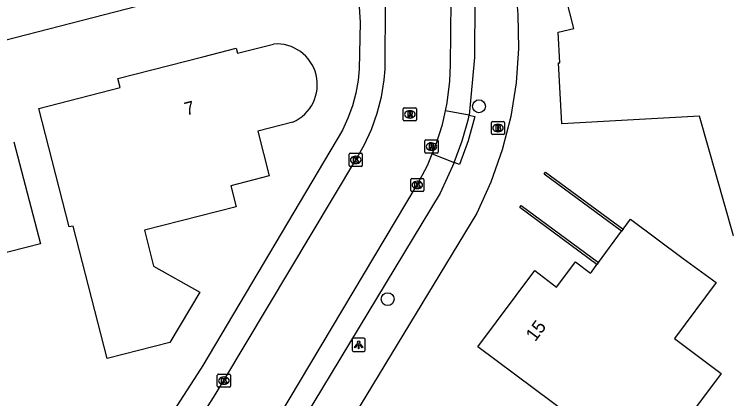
# Model space of a CAD drawing. Extents: x 158838 to 160074, y 386376 to 387776.
# Drawn here: x 159485.7 to 159539.8, y 386691 to 386720.2 of the extents above; entities that cross this region are included whole.
import ezdxf

# ---------------------------------------------------------------- set-up
doc = ezdxf.new("R2010")
doc.units = 0
for name, color, linetype in [('IMGEO_Boom', 7, 'Continuous'), ('IMGEO_Brandkraan', 7, 'Continuous'), ('IMGEO_Kolk', 7, 'Continuous'), ('IMGEO_Lichtpunt', 7, 'Continuous'), ('IMGEO_Muur', 7, 'Continuous'), ('IMGEO_Pand', 7, 'Continuous'), ('IMGEO_Pand_nummerreeks', 7, 'Continuous'), ('IMGEO_Rijbaan_lokaal_gesloten', 7, 'Continuous'), ('IMGEO_Rioolput', 7, 'Continuous'), ('IMGEO_Voetpad_open', 7, 'Continuous')]:
    doc.layers.add(name, color=color, linetype=linetype)

msp = doc.modelspace()

# ---------------------------------------------------------------- linework, layer by layer
at = {"layer": 'IMGEO_Boom'}
for centre in [(159520.987, 386713.228), (159514.05, 386698.566)]:
    msp.add_circle(centre, 0.489, dxfattribs=at)
at = {"layer": 'IMGEO_Brandkraan'}
for p, q in [((159521.933, 386711.149), (159521.933, 386712.001)), ((159522.008, 386712.075), (159522.86, 386712.075)), ((159522.421, 386711.855), (159522.446, 386711.855)), ((159522.934, 386712.001), (159522.934, 386711.149)), ((159522.86, 386711.075), (159522.008, 386711.075)), ((159522.444, 386711.295), (159522.419, 386711.295))]:
    msp.add_line(p, q, dxfattribs=at)
for points in [[(159521.933, 386711.149), (159521.933, 386712.001)], [(159522.008, 386712.075), (159522.86, 386712.075)], [(159522.281, 386711.775), (159522.281, 386711.375), (159522.494, 386711.375)], [(159522.512, 386711.775), (159522.281, 386711.775)], [(159522.46, 386711.694), (159522.406, 386711.694), (159522.406, 386711.618)], [(159522.406, 386711.618), (159522.459, 386711.618)], [(159522.934, 386712.001), (159522.934, 386711.149)], [(159522.86, 386711.075), (159522.008, 386711.075)], [(159522.468, 386711.542), (159522.406, 386711.542), (159522.406, 386711.461)], [(159522.406, 386711.461), (159522.468, 386711.461)]]:
    msp.add_lwpolyline(points, dxfattribs=at)
for centre, radius, start, end in [((159522.01, 386711.999), 0.0765, 91.552, 178.448), ((159522.01, 386711.999), 0.0765, 91.552, 178.448), ((159522.461, 386711.656), 0.0379, 267.8285, 90.9355), ((159522.516, 386711.63), 0.145, 59.4692, 91.5367), ((159522.541, 386711.677), 0.0922, 285.5137, 58.1501), ((159522.546, 386711.485), 0.105, 301.3115, 78.989), ((159522.858, 386711.999), 0.0765, 1.552, 88.448), ((159522.858, 386711.999), 0.0765, 1.552, 88.448), ((159522.01, 386711.151), 0.0765, 181.552, 268.448), ((159522.01, 386711.151), 0.0765, 181.552, 268.448), ((159522.469, 386711.501), 0.0404, 269.8759, 90.5077), ((159522.5, 386711.626), 0.251, 268.6676, 293.5347), ((159522.858, 386711.151), 0.0765, 271.552, 358.448), ((159522.858, 386711.151), 0.0765, 271.552, 358.448)]:
    msp.add_arc(centre, radius, start, end, dxfattribs=at)
for centre, major_axis, ratio, start_param, end_param in [((159522.42, 386711.575), (-0.387, 0.002), 0.722429, 4.712389, 7.853982), ((159522.445, 386711.575), (-0.39, 0.002), 0.717154, 1.570796, 4.712389)]:
    msp.add_ellipse(centre, major_axis=major_axis, ratio=ratio, start_param=start_param, end_param=end_param, dxfattribs=at)
at = {"layer": 'IMGEO_Kolk'}
for p, q in [((159511.123, 386708.725), (159511.123, 386709.577)), ((159511.198, 386709.651), (159512.05, 386709.651)), ((159511.611, 386709.431), (159511.636, 386709.431)), ((159512.124, 386709.577), (159512.124, 386708.725)), ((159512.05, 386708.651), (159511.198, 386708.651)), ((159511.634, 386708.871), (159511.609, 386708.871)), ((159515.803, 386706.819), (159515.803, 386707.671)), ((159515.878, 386707.745), (159516.73, 386707.745)), ((159516.291, 386707.525), (159516.316, 386707.525)), ((159516.804, 386707.671), (159516.804, 386706.819)), ((159516.73, 386706.745), (159515.878, 386706.745)), ((159516.314, 386706.965), (159516.289, 386706.965)), ((159501.108, 386691.946), (159501.108, 386692.798)), ((159501.183, 386692.872), (159502.035, 386692.872)), ((159501.596, 386692.652), (159501.621, 386692.652)), ((159502.109, 386692.798), (159502.109, 386691.946)), ((159501.619, 386692.092), (159501.594, 386692.092)), ((159502.035, 386691.872), (159501.183, 386691.872))]:
    msp.add_line(p, q, dxfattribs=at)
for points in [[(159511.123, 386708.725), (159511.123, 386709.577)], [(159511.198, 386709.651), (159512.05, 386709.651)], [(159512.124, 386709.577), (159512.124, 386708.725)], [(159511.444, 386709.351), (159511.567, 386709.351), (159511.567, 386709.2), (159511.697, 386709.351), (159511.861, 386709.351), (159511.715, 386709.2), (159511.868, 386708.951), (159511.716, 386708.951), (159511.631, 386709.115), (159511.567, 386709.048), (159511.567, 386708.951), (159511.444, 386708.951), (159511.444, 386709.351)], [(159512.05, 386708.651), (159511.198, 386708.651)], [(159515.803, 386706.819), (159515.803, 386707.671)], [(159515.878, 386707.745), (159516.73, 386707.745)], [(159516.124, 386707.445), (159516.247, 386707.445), (159516.247, 386707.294), (159516.377, 386707.445), (159516.541, 386707.445), (159516.395, 386707.294), (159516.548, 386707.045), (159516.396, 386707.045), (159516.311, 386707.209), (159516.247, 386707.142), (159516.247, 386707.045), (159516.124, 386707.045), (159516.124, 386707.445)], [(159516.804, 386707.671), (159516.804, 386706.819)], [(159516.73, 386706.745), (159515.878, 386706.745)], [(159501.108, 386691.946), (159501.108, 386692.798)], [(159501.183, 386692.872), (159502.035, 386692.872)], [(159502.109, 386692.798), (159502.109, 386691.946)], [(159501.429, 386692.572), (159501.552, 386692.572), (159501.552, 386692.421), (159501.682, 386692.572), (159501.846, 386692.572), (159501.7, 386692.421), (159501.853, 386692.172), (159501.701, 386692.172), (159501.616, 386692.336), (159501.552, 386692.269), (159501.552, 386692.172), (159501.429, 386692.172), (159501.429, 386692.572)], [(159502.035, 386691.872), (159501.183, 386691.872)]]:
    msp.add_lwpolyline(points, dxfattribs=at)
for centre, start, end in [((159511.2, 386709.575), 91.552, 178.448), ((159511.2, 386709.575), 91.552, 178.448), ((159512.048, 386709.575), 1.552, 88.448), ((159512.048, 386709.575), 1.552, 88.448), ((159511.2, 386708.727), 181.552, 268.448), ((159511.2, 386708.727), 181.552, 268.448), ((159512.048, 386708.727), 271.552, 358.448), ((159512.048, 386708.727), 271.552, 358.448), ((159515.88, 386707.669), 91.552, 178.448), ((159515.88, 386707.669), 91.552, 178.448), ((159516.728, 386707.669), 1.552, 88.448), ((159516.728, 386707.669), 1.552, 88.448), ((159515.88, 386706.821), 181.552, 268.448), ((159515.88, 386706.821), 181.552, 268.448), ((159516.728, 386706.821), 271.552, 358.448), ((159516.728, 386706.821), 271.552, 358.448), ((159501.185, 386692.796), 91.552, 178.448), ((159501.185, 386692.796), 91.552, 178.448), ((159502.033, 386692.796), 1.552, 88.448), ((159502.033, 386692.796), 1.552, 88.448), ((159501.185, 386691.948), 181.552, 268.448), ((159501.185, 386691.948), 181.552, 268.448), ((159502.033, 386691.948), 271.552, 358.448), ((159502.033, 386691.948), 271.552, 358.448)]:
    msp.add_arc(centre, 0.0765, start, end, dxfattribs=at)
for centre, major_axis, ratio, start_param, end_param in [((159511.61, 386709.151), (-0.387, 0.002), 0.722429, 4.712389, 7.853982), ((159511.635, 386709.151), (-0.39, 0.002), 0.717154, 1.570796, 4.712389), ((159516.29, 386707.245), (-0.387, 0.002), 0.722429, 4.712389, 7.853982), ((159516.315, 386707.245), (-0.39, 0.002), 0.717154, 1.570796, 4.712389), ((159501.595, 386692.372), (-0.387, 0.002), 0.722429, 4.712389, 7.853982), ((159501.62, 386692.372), (-0.39, 0.002), 0.717154, 1.570796, 4.712389)]:
    msp.add_ellipse(centre, major_axis=major_axis, ratio=ratio, start_param=start_param, end_param=end_param, dxfattribs=at)
at = {"layer": 'IMGEO_Lichtpunt'}
for p, q in [((159511.347, 386695.499), (159511.347, 386694.692)), ((159511.347, 386695.499), (159511.347, 386694.692)), ((159512.249, 386695.594), (159511.441, 386695.594)), ((159512.249, 386695.594), (159511.441, 386695.594)), ((159512.343, 386694.692), (159512.343, 386695.499)), ((159512.343, 386694.692), (159512.343, 386695.499)), ((159511.441, 386694.598), (159512.249, 386694.598)), ((159511.441, 386694.598), (159512.249, 386694.598))]:
    msp.add_line(p, q, dxfattribs=at)
for points in [[(159511.721, 386695.163), (159511.76, 386695.135), (159511.572, 386694.873), (159511.534, 386694.9), (159511.721, 386695.163)], [(159511.823, 386695.115), (159511.87, 386695.115), (159511.87, 386694.793), (159511.823, 386694.793), (159511.823, 386695.115)], [(159511.933, 386695.135), (159511.971, 386695.162), (159512.158, 386694.9), (159512.119, 386694.872), (159511.933, 386695.135)]]:
    msp.add_lwpolyline(points, dxfattribs=at)
msp.add_circle((159511.846, 386695.297), 0.0994, dxfattribs=at)
for centre, start, end in [((159511.441, 386695.499), 90, 180), ((159511.441, 386695.499), 90, 180), ((159512.249, 386695.499), 0, 90), ((159512.249, 386695.499), 0, 90), ((159511.441, 386694.692), 180, 270), ((159511.441, 386694.692), 180, 270), ((159512.249, 386694.692), 270, 0), ((159512.249, 386694.692), 270, 360)]:
    msp.add_arc(centre, 0.0946, start, end, dxfattribs=at)
at = {"layer": 'IMGEO_Muur'}
for points in [[(159531.824, 386703.734), (159525.942, 386708.073), (159526.048, 386708.213), (159531.942, 386703.893)], [(159529.95, 386701.192), (159524.08, 386705.521), (159524.184, 386705.68), (159530.062, 386701.345)]]:
    msp.add_lwpolyline(points, dxfattribs=at)
at = {"layer": 'IMGEO_Pand'}
for points in [[(159546.149, 386705.02), (159540.327, 386703.374), (159537.752, 386712.48), (159532.281, 386712.169), (159527.289, 386711.885), (159527.025, 386716.527), (159527.131, 386716.528), (159526.993, 386718.851), (159528.19, 386719.148), (159526.968, 386723.917), (159533.73, 386725.646), (159533.978, 386724.677), (159536.711, 386725.424), (159540.305, 386726.406), (159541.623, 386721.583), (159546.149, 386705.02)], [(159487.54, 386713.069), (159493.724, 386714.655), (159493.557, 386715.329), (159500, 386716.992), (159502.548, 386717.65), (159502.648, 386717.262), (159505.369, 386717.958)], [(159506.842, 386712.025), (159504.174, 386711.333), (159505.041, 386707.931), (159502.142, 386707.192), (159502.549, 386705.593), (159495.577, 386703.817), (159496.269, 386701.084), (159499.767, 386699.087), (159497.488, 386695.274), (159492.734, 386694.053), (159490.144, 386704.126), (159489.853, 386704.051), (159487.54, 386713.069)], [(159485.637, 386710.52), (159487.661, 386702.78), (159484.167, 386701.875)], [(159531.942, 386703.893), (159532.489, 386704.635), (159536.513, 386701.667), (159539.016, 386699.821), (159535.837, 386695.571), (159539.38, 386692.921), (159533.731, 386685.37), (159520.906, 386694.932), (159525.234, 386700.736), (159526.889, 386699.484), (159528.185, 386701.234), (159528.311, 386701.404), (159529.466, 386700.536), (159529.526, 386700.618), (159529.95, 386701.192)], [(159530.062, 386701.345), (159531.824, 386703.734)], [(159531.942, 386703.893), (159531.824, 386703.734)], [(159530.062, 386701.345), (159529.95, 386701.192)]]:
    msp.add_lwpolyline(points, dxfattribs=at)
msp.add_arc((159505.603, 386714.867), 3.1, 293.5507, 94.3354, dxfattribs=at)
at = {"layer": 'IMGEO_Rijbaan_lokaal_gesloten'}
for points in [[(159499.36, 386688.811), (159500, 386689.822), (159500.806, 386691.095), (159501.61, 386692.371), (159511.626, 386709.15), (159512.275, 386710.281), (159512.821, 386711.465), (159513.258, 386712.692), (159513.584, 386713.955), (159513.796, 386715.241), (159513.869, 386716.038), (159513.878, 386721.278), (159513.757, 386723.28), (159513.538, 386725.199)], [(159518.439, 386712.887), (159518.568, 386713.481), (159518.776, 386715.135), (159518.834, 386716.37), (159518.864, 386721.239), (159518.731, 386723.49), (159518.576, 386725.587)], [(159517.443, 386709.606), (159517.715, 386710.261), (159518.213, 386711.852), (159518.439, 386712.887)], [(159502.694, 386684.743), (159505.787, 386689.619), (159516.302, 386707.245), (159517.076, 386708.722), (159517.443, 386709.606)]]:
    msp.add_lwpolyline(points, dxfattribs=at)
at = {"layer": 'IMGEO_Rioolput'}
for p, q in [((159515.239, 386712.186), (159515.239, 386713.038)), ((159515.314, 386713.112), (159516.166, 386713.112)), ((159515.727, 386712.892), (159515.752, 386712.892)), ((159516.24, 386713.038), (159516.24, 386712.186)), ((159515.75, 386712.332), (159515.725, 386712.332)), ((159516.166, 386712.112), (159515.314, 386712.112)), ((159516.877, 386709.739), (159516.877, 386710.591)), ((159516.952, 386710.665), (159517.804, 386710.665)), ((159517.878, 386710.591), (159517.878, 386709.739)), ((159517.365, 386710.445), (159517.39, 386710.445)), ((159517.804, 386709.665), (159516.952, 386709.665)), ((159517.388, 386709.885), (159517.363, 386709.885))]:
    msp.add_line(p, q, dxfattribs=at)
for points in [[(159515.239, 386712.186), (159515.239, 386713.038)], [(159515.314, 386713.112), (159516.166, 386713.112)], [(159515.828, 386712.81), (159515.576, 386712.812), (159515.576, 386712.412)], [(159515.754, 386712.731), (159515.7, 386712.731), (159515.7, 386712.65)], [(159516.24, 386713.038), (159516.24, 386712.186)], [(159515.576, 386712.412), (159515.7, 386712.412), (159515.7, 386712.574), (159515.711, 386712.574)], [(159515.7, 386712.65), (159515.752, 386712.65)], [(159515.758, 386712.545), (159515.829, 386712.412), (159515.969, 386712.412), (159515.904, 386712.538)], [(159516.166, 386712.112), (159515.314, 386712.112)], [(159516.877, 386709.739), (159516.877, 386710.591)], [(159516.952, 386710.665), (159517.804, 386710.665)], [(159517.878, 386710.591), (159517.878, 386709.739)], [(159517.466, 386710.363), (159517.214, 386710.365), (159517.214, 386709.965)], [(159517.214, 386709.965), (159517.338, 386709.965), (159517.338, 386710.127), (159517.349, 386710.127)], [(159517.392, 386710.284), (159517.338, 386710.284), (159517.338, 386710.203)], [(159517.338, 386710.203), (159517.39, 386710.203)], [(159517.396, 386710.098), (159517.467, 386709.965), (159517.607, 386709.965), (159517.542, 386710.091)], [(159517.804, 386709.665), (159516.952, 386709.665)]]:
    msp.add_lwpolyline(points, dxfattribs=at)
for centre, radius, start, end in [((159515.316, 386713.036), 0.0765, 91.552, 178.448), ((159515.316, 386713.036), 0.0765, 91.552, 178.448), ((159515.76, 386712.635), 0.0964, 77.0061, 93.1865), ((159515.774, 386712.692), 0.0378, 276.6634, 79.6772), ((159515.827, 386712.7), 0.109, 350.3612, 89.416), ((159515.825, 386712.7), 0.112, 277.5842, 350.9817), ((159516.164, 386713.036), 0.0765, 1.552, 88.448), ((159516.164, 386713.036), 0.0765, 1.552, 88.448), ((159515.316, 386712.188), 0.0765, 181.552, 268.448), ((159515.316, 386712.188), 0.0765, 181.552, 268.448), ((159515.71, 386712.521), 0.0533, 26.0293, 88.6989), ((159515.736, 386712.839), 0.19, 274.7715, 282.9687), ((159515.809, 386712.485), 0.108, 29.5134, 73.7905), ((159516.164, 386712.188), 0.0765, 271.552, 358.448), ((159516.164, 386712.188), 0.0765, 271.552, 358.448), ((159516.954, 386710.589), 0.0765, 91.552, 178.448), ((159516.954, 386710.589), 0.0765, 91.552, 178.448), ((159517.802, 386710.589), 0.0765, 1.552, 88.448), ((159517.802, 386710.589), 0.0765, 1.552, 88.448), ((159517.348, 386710.074), 0.0533, 26.0293, 88.6989), ((159517.374, 386710.392), 0.19, 274.7715, 282.9687), ((159517.398, 386710.188), 0.0964, 77.0061, 93.1865), ((159517.412, 386710.245), 0.0378, 276.6634, 79.6772), ((159517.465, 386710.253), 0.109, 350.3612, 89.416), ((159517.463, 386710.253), 0.112, 277.5842, 350.9817), ((159517.447, 386710.038), 0.108, 29.5134, 73.7905), ((159516.954, 386709.741), 0.0765, 181.552, 268.448), ((159516.954, 386709.741), 0.0765, 181.552, 268.448), ((159517.802, 386709.741), 0.0765, 271.552, 358.448), ((159517.802, 386709.741), 0.0765, 271.552, 358.448)]:
    msp.add_arc(centre, radius, start, end, dxfattribs=at)
for centre, major_axis, ratio, start_param, end_param in [((159515.726, 386712.612), (-0.387, 0.002), 0.722429, 4.712389, 7.853982), ((159515.751, 386712.612), (-0.39, 0.002), 0.717154, 1.570796, 4.712389), ((159517.364, 386710.165), (-0.387, 0.002), 0.722429, 4.712389, 7.853982), ((159517.389, 386710.165), (-0.39, 0.002), 0.717154, 1.570796, 4.712389)]:
    msp.add_ellipse(centre, major_axis=major_axis, ratio=ratio, start_param=start_param, end_param=end_param, dxfattribs=at)
at = {"layer": 'IMGEO_Voetpad_open'}
for points in [[(159524.846, 386728.532), (159523.607, 386726.844), (159523.829, 386721.437), (159523.936, 386720.207), (159523.989, 386717.606), (159523.81, 386715.012), (159523.4, 386712.444), (159522.762, 386709.923), (159521.901, 386707.468), (159520.825, 386705.101), (159506.854, 386682.053), (159500.252, 386671.907), (159500, 386671.529), (159492.426, 386660.371), (159492.025, 386659.896), (159480.297, 386643.692), (159466.865, 386626.712), (159452.919, 386610.024), (159444.818, 386600.823), (159442.679, 386598.473)], [(159518.576, 386725.587), (159518.602, 386725.409), (159518.644, 386725.234), (159518.702, 386725.063), (159518.774, 386724.898), (159518.861, 386724.74), (159518.961, 386724.591), (159519.075, 386724.451), (159519.201, 386724.322), (159519.217, 386724.307), (159520.303, 386723.288), (159520.321, 386723.269), (159520.385, 386723.195), (159520.442, 386723.115), (159520.492, 386723.031), (159520.534, 386722.942), (159520.568, 386722.85), (159520.594, 386722.755), (159520.611, 386722.659), (159520.619, 386722.561), (159520.682, 386721.334), (159520.658, 386716.928), (159520.24, 386712.542)], [(159412.19, 386699.306), (159415.977, 386700.489), (159452.288, 386709.846), (159500, 386722.142), (159509.443, 386724.576), (159509.495, 386724.581), (159509.683, 386724.586), (159509.872, 386724.575), (159510.058, 386724.547), (159510.242, 386724.502), (159510.42, 386724.442), (159510.593, 386724.365), (159510.758, 386724.274), (159510.914, 386724.168), (159511.06, 386724.048), (159511.195, 386723.916), (159511.317, 386723.773), (159511.426, 386723.619), (159511.521, 386723.456), (159511.601, 386723.285), (159511.666, 386723.107), (159511.714, 386722.925)], [(159511.714, 386722.925), (159511.746, 386722.739), (159511.952, 386719.617), (159511.887, 386716.039), (159511.811, 386715.214), (159511.639, 386714.228), (159511.379, 386713.262), (159511.034, 386712.323), (159510.606, 386711.419), (159500, 386693.513), (159499.829, 386693.238), (159489.836, 386677.746), (159489.757, 386677.629)], [(159520.24, 386712.542), (159518.439, 386712.887)], [(159520.24, 386712.542), (159520.663, 386712.461), (159520.172, 386710.6), (159519.507, 386708.793), (159519.101, 386708.953)], [(159519.101, 386708.953), (159519.716, 386710.592), (159520.182, 386712.278), (159520.24, 386712.542)], [(159517.443, 386709.606), (159519.101, 386708.953)], [(159519.101, 386708.953), (159518.046, 386706.634), (159504.259, 386683.831), (159504.222, 386683.773)]]:
    msp.add_lwpolyline(points, dxfattribs=at)

# ---------------------------------------------------------------- texts
at = {"layer": 'IMGEO_Pand_nummerreeks'}
for s, rotation, p in [('7', 13.814, (159498.744, 386712.512)), ('15', 53.2884, (159525.26, 386695.284))]:
    msp.add_text(s, height=1, rotation=rotation, dxfattribs=at).set_placement(p)

doc.saveas('drawing.dxf')
